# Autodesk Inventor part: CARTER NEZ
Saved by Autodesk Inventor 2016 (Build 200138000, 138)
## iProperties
Created: 2013-10
Part Number: CARTER NEZ
Material: Générique
Document SubType Name: Modeling
Designer: Bruno
Density: 1 g/cm^3
Appearance: Par défaut
Author: Bruno
Sending System: SolidWorks 2013
Last Author: christophe
Last Saved: 2014-02-15
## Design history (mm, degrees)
feature "Balayage1"
node "Solide1"
